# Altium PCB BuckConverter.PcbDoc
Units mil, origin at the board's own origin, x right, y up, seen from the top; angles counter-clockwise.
Board outline 3937.01 x 3149.61 mil, 2 copper layers (Top Layer, Bottom Layer); 153 components, 71 nets, 409 pads, 250 vias.
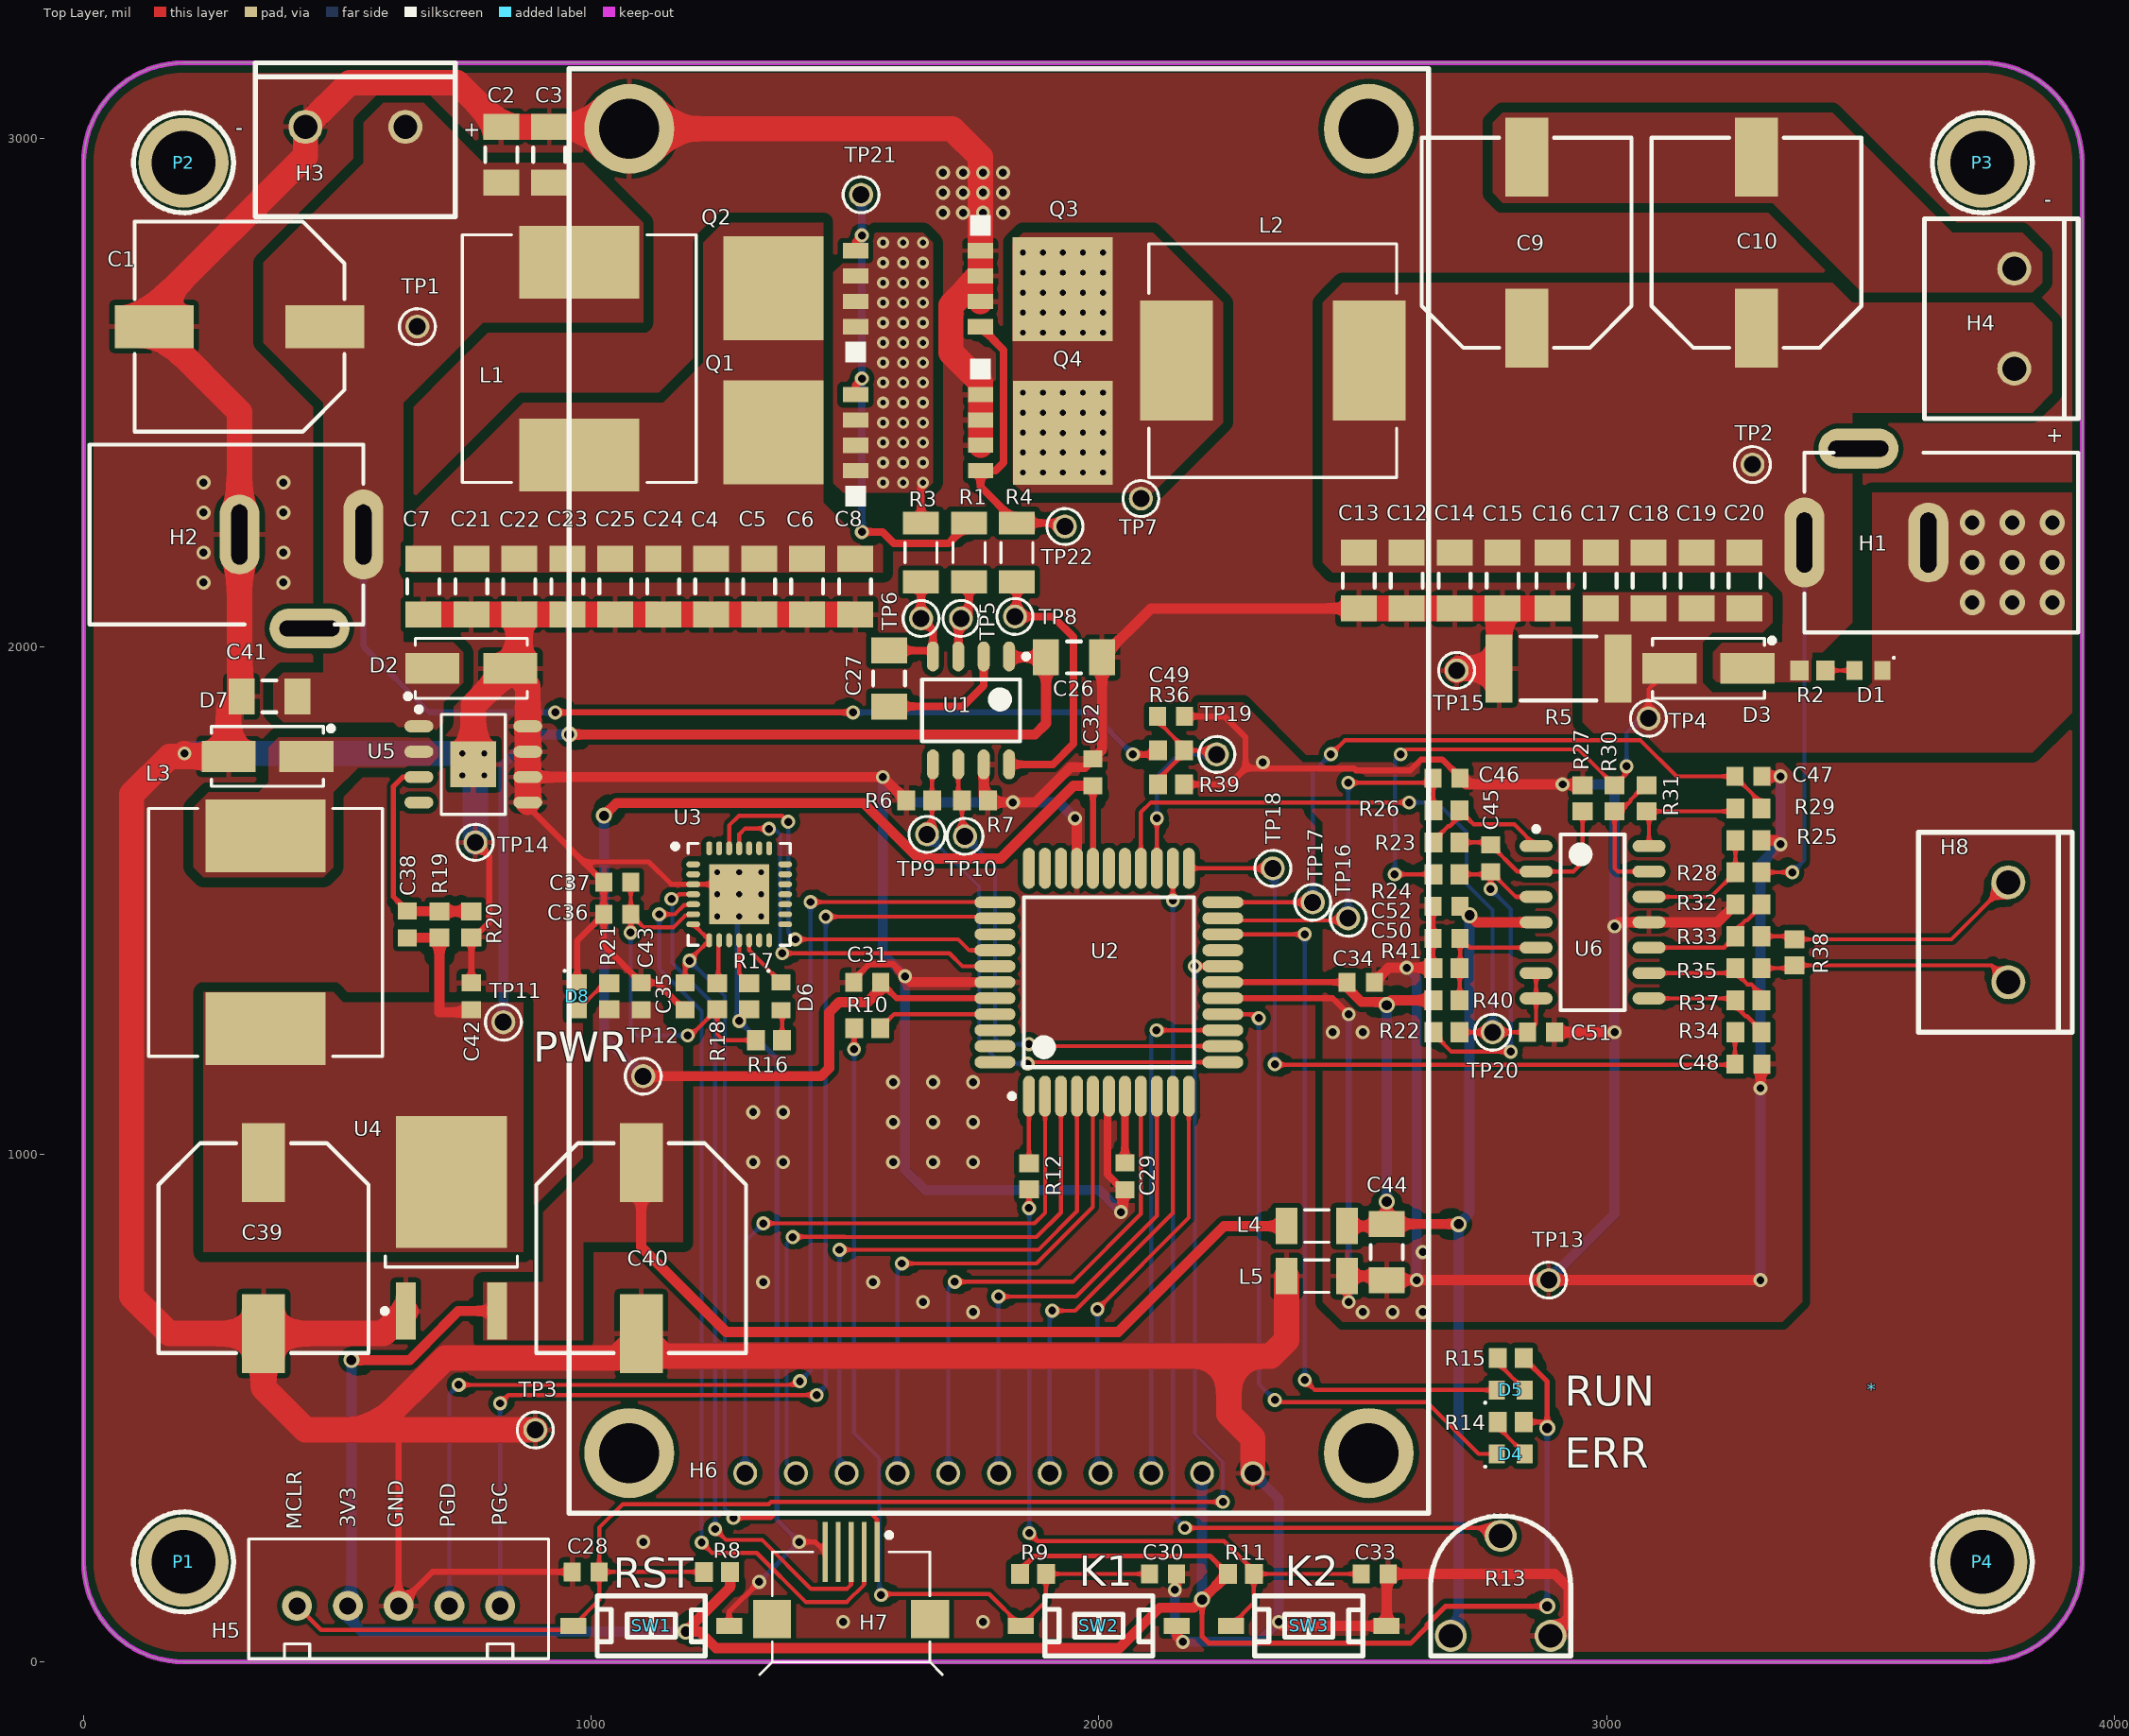
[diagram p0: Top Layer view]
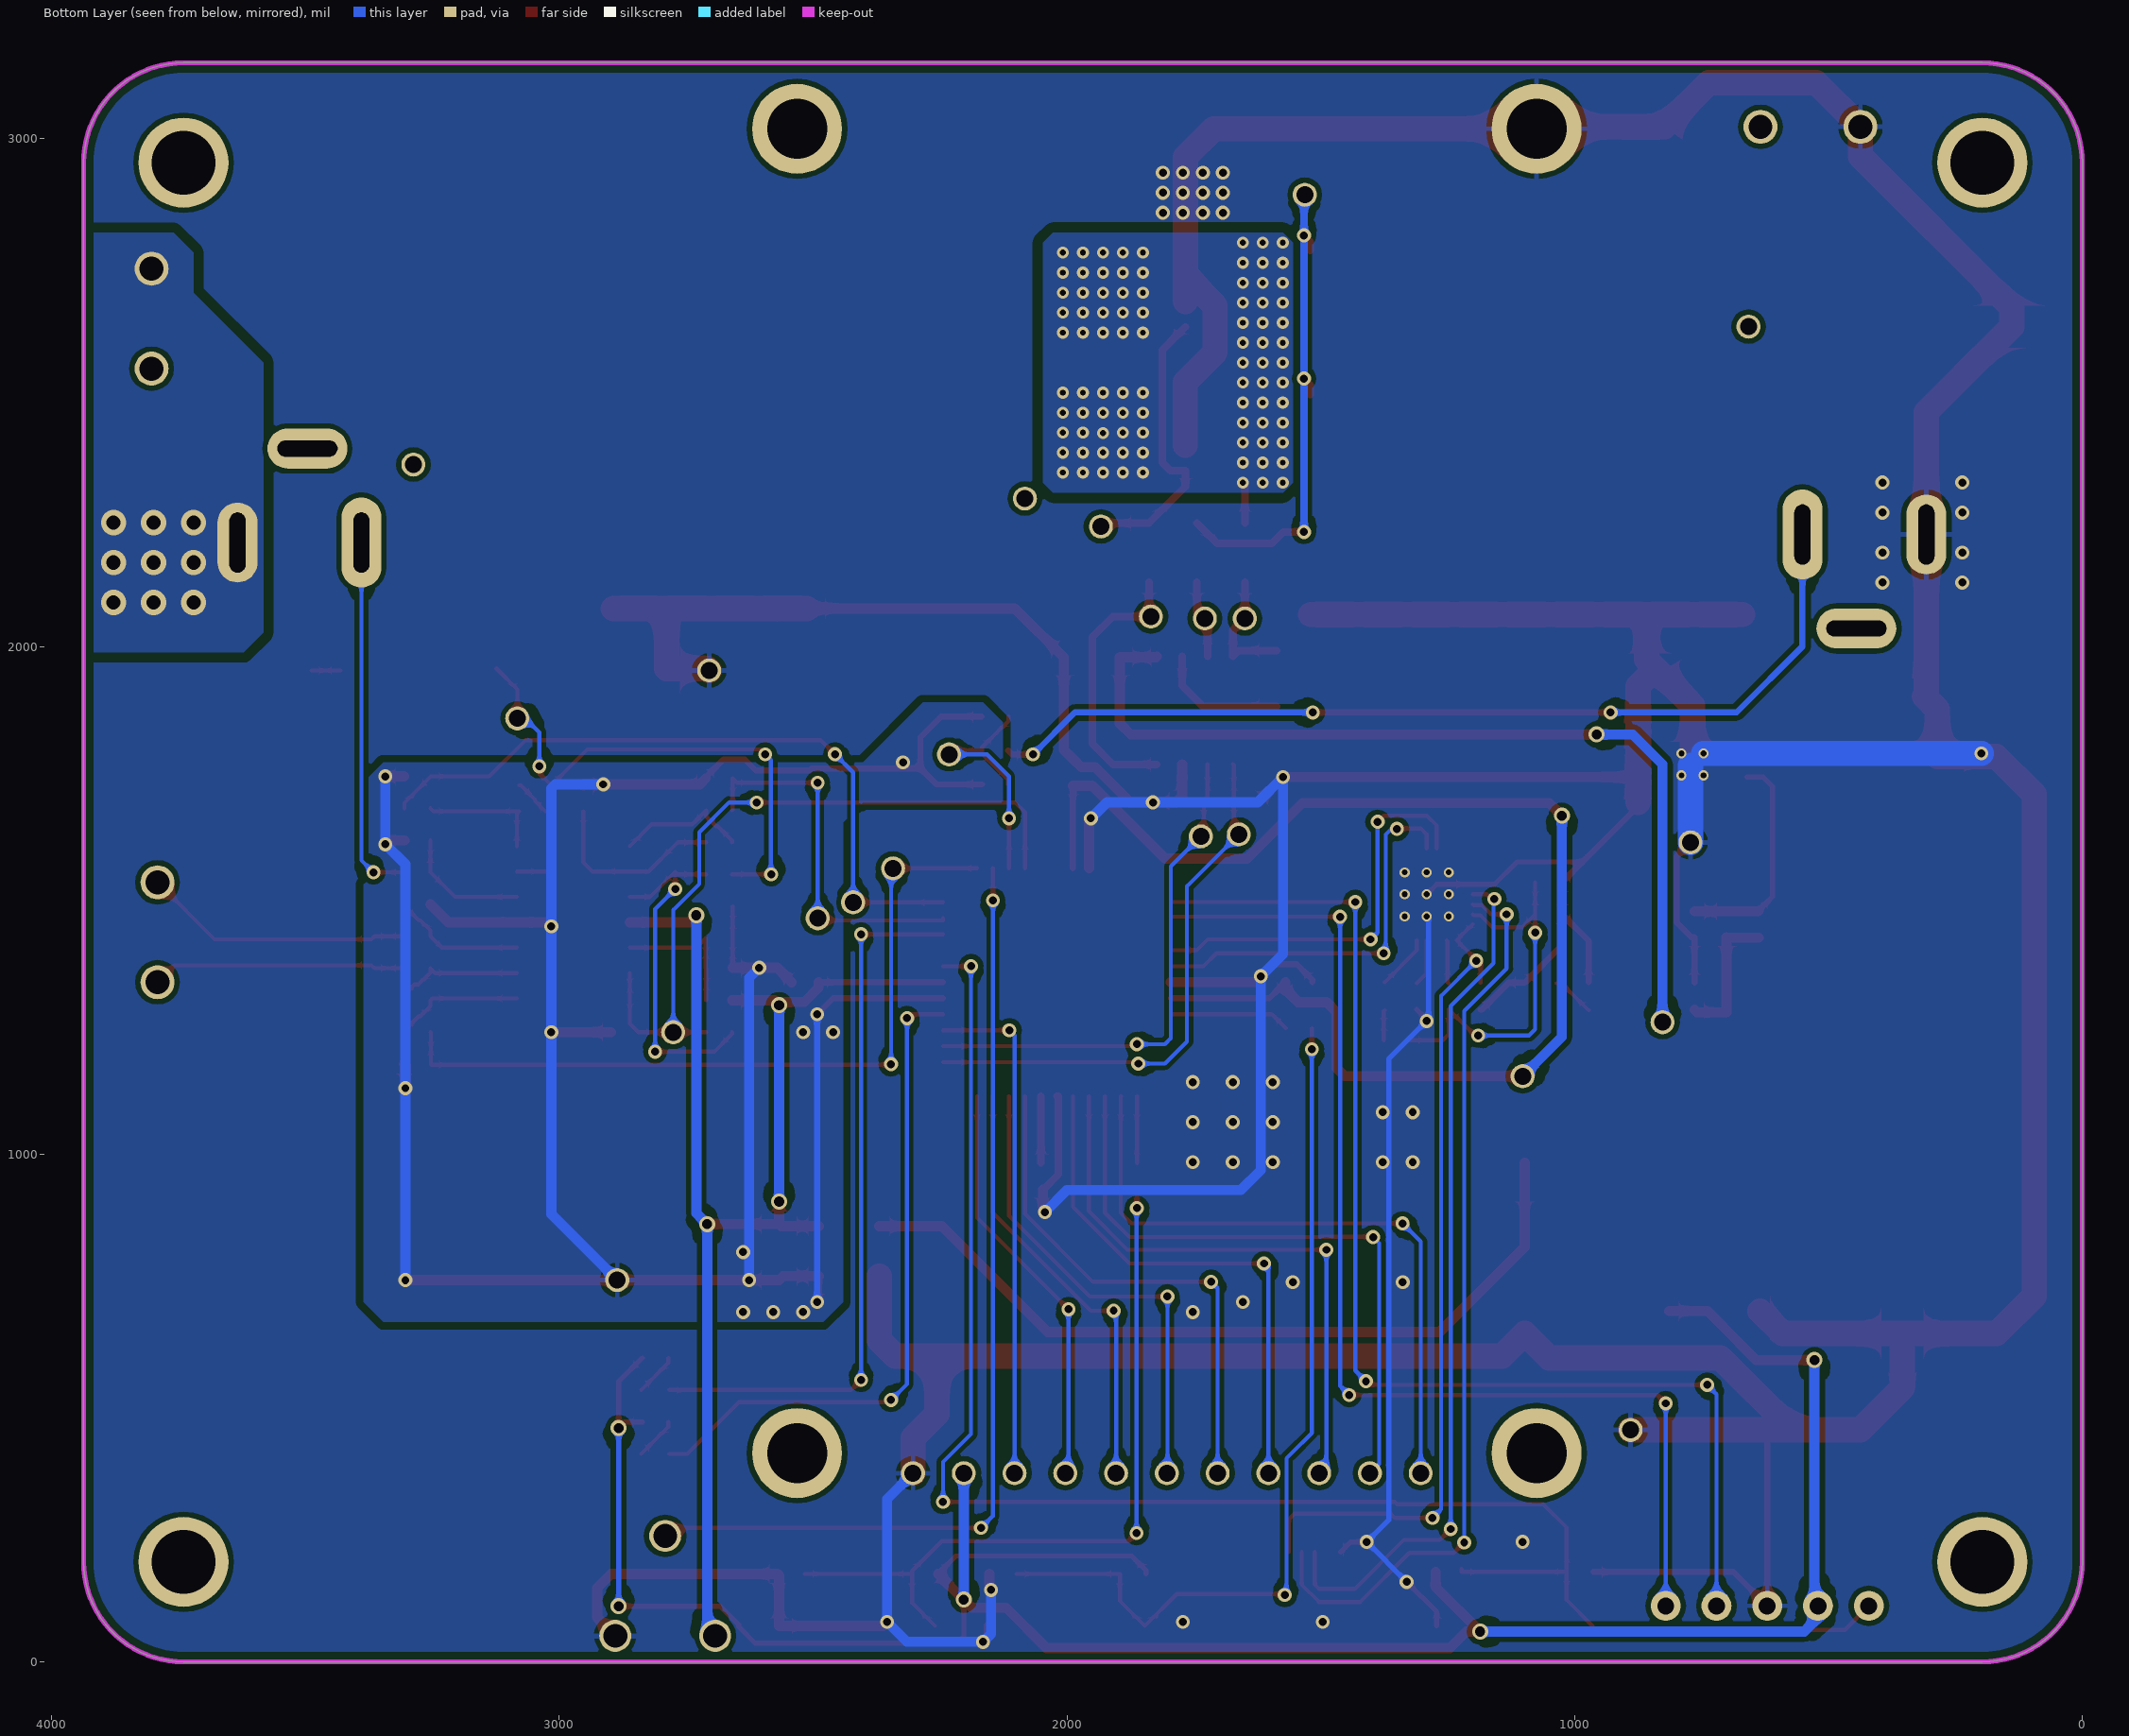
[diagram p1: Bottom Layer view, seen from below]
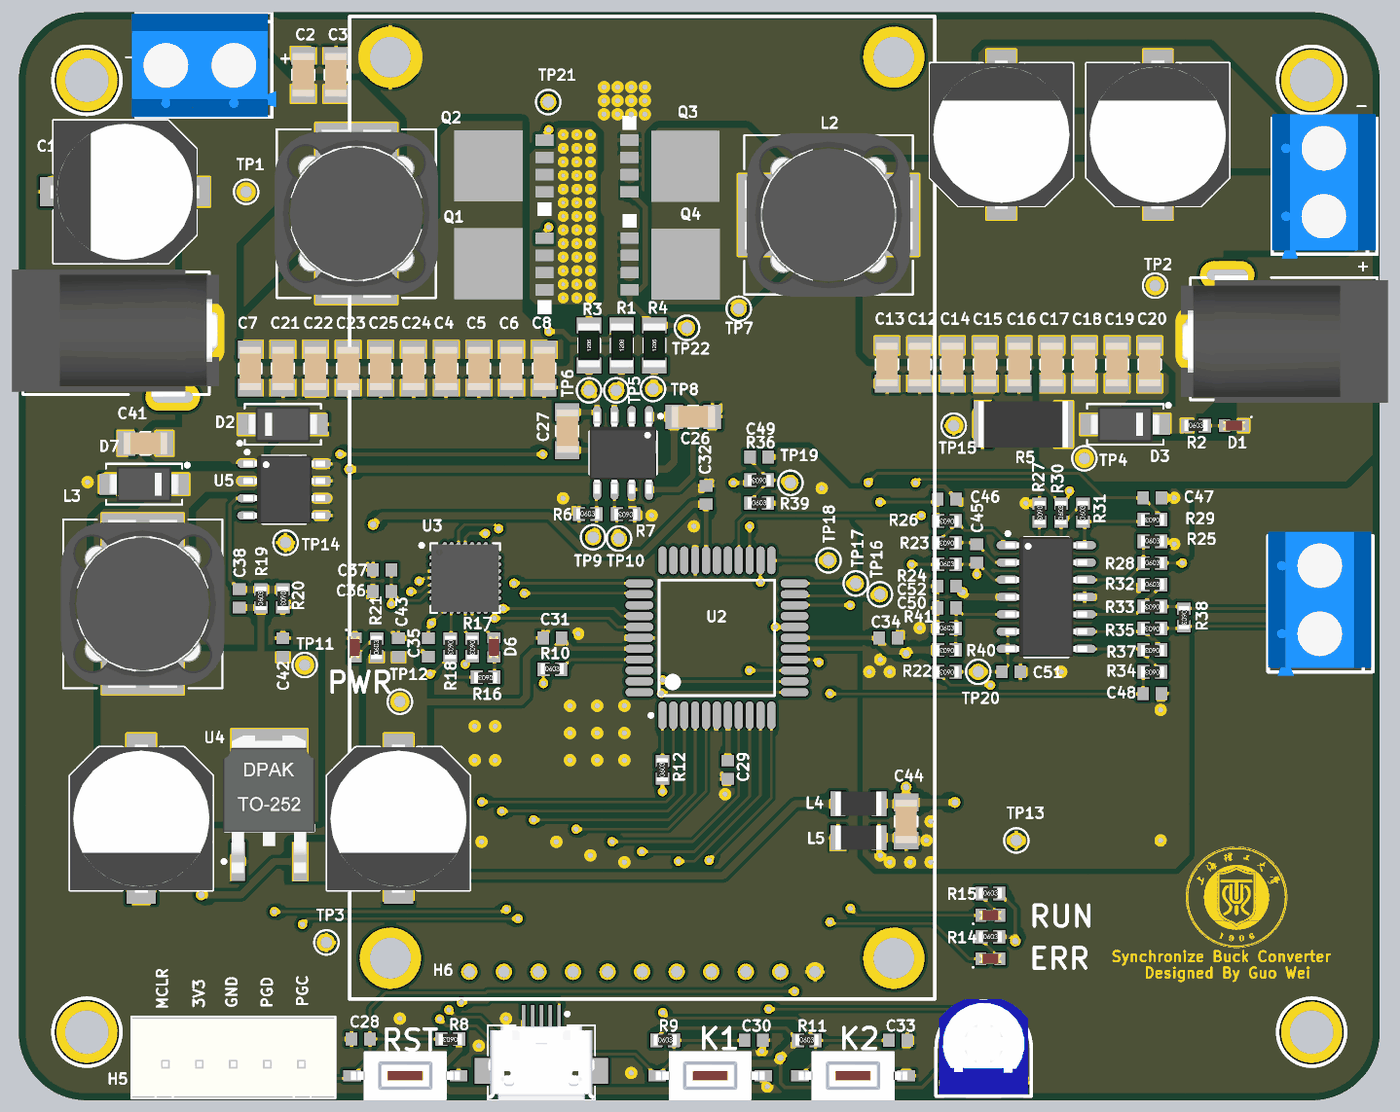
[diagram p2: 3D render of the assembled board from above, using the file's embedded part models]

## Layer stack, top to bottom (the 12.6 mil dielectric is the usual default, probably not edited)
Top Solder: solder mask 0.4, Solder Resist, Dk 3.5
Top Layer: signal copper 1.4
Dielectric 1: dielectric 12.6, FR-4, Dk 4.8
Bottom Layer: signal copper 1.4
Bottom Solder: solder mask 0.4, Solder Resist, Dk 3.5

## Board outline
0,196.85 0,2952.76 cw(c196.85,2952.76) 196.85,3149.61 3740.16,3149.61 cw(c3740.16,2952.76) 3937.01,2952.76 3937.01,196.85 cw(c3740.16,196.85) 3740.16,0 196.85,0 cw(c196.85,196.85)

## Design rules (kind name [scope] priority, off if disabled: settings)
BoardOutlineClearance [All] p1: gap=10 ignorepadtopadclearanceinfootprint=FALSE except(0: Arc-SplitContinuation Track-SplitContinuation SMDPad-SplitContinuation THPad-SplitContinuation Via-SplitContinuation Fill-SplitContinuation Poly-SplitContinuation Region-SplitContinuation Text-SplitContinuation; 19.68: Poly-OutlineEdge Poly-CavityEdge Poly-CutoutEdge Poly-SplitBarrior)
Clearance Power_Clearance [InNetClass('POWER')] p1: gap=10 ignorepadtopadclearanceinfootprint=FALSE except(0: Arc-Hole Track-Hole SMDPad-Hole THPad-Hole Via-Hole Fill-Hole Poly-Hole Region-Hole Text-Hole; 6: SMDPad-SMDPad; 20: Fill-Fill Fill-Poly Fill-Region Poly-Poly Poly-Region Region-Region)
Clearance [All] p2: gap=10 ignorepadtopadclearanceinfootprint=FALSE except(6: SMDPad-SMDPad; 8: Arc-Arc Arc-Track Arc-SMDPad Arc-THPad Arc-Via Arc-Fill Arc-Poly Arc-Region Arc-Text Arc-Hole Track-Track Track-SMDPad Track-THPad Track-Via Track-Fill Track-Poly Track-Region Track-Text Track-Hole SMDPad-THPad THPad-THPad; 15: Fill-Fill Fill-Poly Fill-Region Poly-Poly Poly-Region Region-Region)
ComponentClearance [All] p1 off: gap=10 collisioncheckmode=3 verticalgap=10 showdistances=FALSE
Height [All] p1 off: minheight=0 maxheight=1000 prefheight=500
HoleSize [All] p1: absolutevalues=TRUE maxlimit=1100 minlimit=0.98 maxpercent=80.000 minpercent=20.000
MinimumSolderMaskSliver [InComponent('*')] p1: minsoldermaskwidth=0
PlaneConnect Power [InNetClass('POWER')] p1: planeconnectstyle=Direct reliefexpansion=20 reliefentries=4 reliefconductorwidth=10 reliefairgap=10
PlaneConnect [All] p2: planeconnectstyle=Relief reliefexpansion=20 reliefentries=4 reliefconductorwidth=10 reliefairgap=10
PolygonConnect PolygonConnect_1 [IsVia] p1: connectstyle=Direct reliefconductorwidth=10 reliefentries=4 polygonreliefangle="90 Angle" airgapwidth=10
PolygonConnect Power_Con [InNetClass('POWER')] p2: connectstyle=Direct reliefconductorwidth=10 reliefentries=4 polygonreliefangle="90 Angle" airgapwidth=10
PolygonConnect [All] p3: connectstyle=Relief reliefconductorwidth=10 reliefentries=4 polygonreliefangle="90 Angle" airgapwidth=10
RoutingVias [All] p1: holewidth=28 width=50 viastyle="Through Hole" minholewidth=11.81 minwidth=23.62 maxholewidth=28 maxwidth=50
SolderMaskExpansion [All] p1: expansion=4
Width [All] p1: maxlimit=100 minlimit=6 preferedwidth=8
25 further rules are at their usual default settings.

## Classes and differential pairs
component class Designator: C45 C46 C47 C48 C49 C50 C51 C52 H8 R22 R23 R24 R25 R26 R27 R28 R29 R30 R31 R32 R33 R34 R35 R36 R37 R38 R39 R40 R41 TP16 TP17 TP18 TP19 TP20 U6
net class POWER: 3V3 9V5 A3V3 NetC1_2 NetC9_1 NetC9_2 NetD7_2 NetL2_1 PV

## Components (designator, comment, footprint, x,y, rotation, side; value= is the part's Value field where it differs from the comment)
* "Logo" USST 3523.62,535.43 r0 top
C1 "100uF" CAPAE109103X105N 307.09,2629.92 r0 top
C2 "22uF" CAP1206 822.83,2968.5 r270 top
C3 "22uF" CAP1206 917.32,2968.5 r270 top
C4 "10uF" CAP1206 1236.22,2118.11 r90 top
C5 "10uF" CAP1206 1330.71,2118.11 r90 top
C6 "10uF" CAP1206 1425.2,2118.11 r90 top
C7 "10uF" CAP1206 669.29,2118.11 r90 top
C8 "10uF" CAP1206 1519.68,2118.11 r90 top
C9 "100uF" CAPAE109103X105N 2842.52,2795.28 r270 top
C10 "100uF" CAPAE109103X105N 3295.28,2795.28 r270 top
C12 "10uF" CAP1206 2606.3,2129.92 r90 top
C13 "10uF" CAP1206 2511.81,2129.92 r90 top
C14 "10uF" CAP1206 2700.79,2129.92 r90 top
C15 "10uF" CAP1206 2795.28,2129.92 r90 top
C16 "10uF" CAP1206 2893.7,2129.92 r90 top
C17 "22uF" CAP1206 2988.19,2129.92 r90 top
C18 "22uF" CAP1206 3082.68,2129.92 r90 top
C19 "10uF" CAP1206 3177.17,2129.92 r90 top
C20 "10uF" CAP1206 3271.65,2129.92 r90 top
C21 "10uF" CAP1206 763.78,2118.11 r90 top
C22 "10uF" CAP1206 858.27,2118.11 r90 top
C23 "10uF" CAP1206 952.76,2118.11 r90 top
C24 "10uF" CAP1206 1141.73,2118.11 r90 top
C25 "10uF" CAP1206 1047.24,2118.11 r90 top
C26 "4.7uF" CAP1206 1951,1978.6 r180 top
C27 "4.7uF" CAP1206 1586.61,1937.01 r270 top
C28 "DNP" CAP0603 989.17,177.17 r0 top
C29 "10uF" CAP0603 2051.18,956.69 r270 top
C30 "0.1uF" CAP0603 2125.98,173.23 r0 top
C31 "0.1uF" CAP0603 1543.31,1338.58 r180 top
C32 "0.1uF" CAP0603 1988.19,1751.97 r90 top
C33 "0.1uF" CAP0603 2543.31,173.23 r0 top
C34 "0.1uF" CAP0603 2515.75,1338.58 r0 top
C35 "1uF" CAP0603 1185.04,1311.02 r90 top
C36 "4.7uF" CAP0603 1051.18,1472.44 r0 top
C37 "0.1uF" CAP0603 1051.18,1535.43 r0 top
C38 "33nF" CAP0603 637.8,1452.76 r90 top
C39 "100uF" CAPAE109103X105N 354.33,814.96 r90 top
C40 "100uF" CAPAE109103X105N 1098.43,814.96 r90 top
C41 "10uF" CAP1206 366.14,1901.57 r0 top
C42 "0.1uF" CAP0603 763.78,1311.02 r90 top
C43 "0.1uF" CAP0603 1098.43,1311.02 r90 top
C44 "22uF" CAP1206 2566.93,807.09 r270 top
C45 "DNP" CAP0603 2771.65,1582.68 r90 top
C46 "10nF" CAP0603 2685.04,1740.16 r0 top
C47 "10nF" CAP0603 3279.53,1744.09 r0 top
C48 "10nF" CAP0603 3279.53,1177.17 r0 top
C49 "10nF" CAP0603 2141.73,1862.2 r0 top
C50 "0.1uF" CAP0603 2685.04,1425.2 r180 top
C51 "0.1uF" CAP0603 2871.06,1240.16 r0 top
C52 "0.1uF" CAP0603 2685.04,1488.19 r180 top
D1 "PWR" LED0603 3515.75,1952.76 r0 top
D2 "SMAJ90A" SMA 763.78,1956.69 r180 top
D3 "SMAJ90A" SMA 3200.79,1956.69 r0 top
D4 "ERR" LED0603 2811.02,409.45 r180 top
D5 "RUN" LED0603 2811.02,535.43 r180 top
D6 "LED" LED0603 1374.02,1311.02 r90 top
D7 "SS310" SMA 362.2,1783.46 r0 top
D8 "PWR" LED0603 972.44,1311.02 r90 top
H1 "PWR-2.5" PWR-2.5 3633.86,2204.72 r180 top
H2 "PWR-2.5" PWR-2.5 307.09,2220.47 r0 top
H3 "" KF301 535.43,3023.62 r180 top
H4 "" KF301 3803.15,2645.67 r90 top
H5 "xh2.54" XH2.54_5A 620.47,110.24 r0 top
H6 "LCD" LCD-2.4' 2303.15,371.65 r90 top
H7 "USB-5p" USB_Micro 1511.81,-0.31 r270 top
H8 "" KF301 3791.34,1437.01 r90 top
L1 "10uH" CDRH125 976.38,2566.93 r270 top
L2 "15uH" CDRH125 2342.52,2562.99 r0 top
L3 "100uH" CDRH125 358.27,1437.01 r270 top
L4 "Inductor" IND1206 2429.13,858.27 r0 top
L5 "Inductor" IND1206 2429.13,759.84 r0 top
P1 "Pad" PAD320R450 196.85,196.85 r0 top
P2 "Pad" PAD320R450 196.85,2952.76 r0 top
P3 "Pad" PAD320R450 3740.16,2952.76 r0 top
P4 "Pad" PAD320R450 3740.16,196.85 r0 top
Q1 "BSC123N08NS3G" QFN5x6 1405.52,2421.06 r90 top
Q2 "BSC123N08NS3G" QFN5x6 1405.52,2704.69 r90 top
Q3 "BSC123N08NS3G" QFN5x6 1881.5,2704.69 r270 top
Q4 "BSC123N08NS3G" QFN5x6 1881.89,2421.26 r270 top
R1 "2R" RES1206 1744.09,2185.04 r90 top
R2 "2k" RES0603 3405.51,1952.76 r0 top
R3 "2R" RES1206 1649.61,2185.04 r90 top
R4 "2R" RES1206 1838.58,2185.04 r90 top
R5 "R050" RESC6432X07N 2905.51,1956.69 r0 top
R6 "10k" RES0603 1645.67,1696.85 r0 top
R7 "10k" RES0603 1755.91,1696.85 r180 top
R8 "10k" RES0603 1248.03,177.17 r180 top
R9 "10k" RES0603 1870.08,173.23 r0 top
R10 "0R" RES0603 1543.31,1248.03 r0 top
R11 "10k" RES0603 2279.53,173.23 r0 top
R12 "0R" RES0603 1862.2,956.69 r90 top
R13 "RPot" RM065 2791.34,287.4 r0 top
R14 "470R" RES0603 2811.02,472.44 r0 top
R15 "470R" RES0603 2811.02,598.43 r0 top
R16 "1k" RES0603 1350.39,1224.41 r180 top
R17 "10k" RES0603 1311.02,1311.02 r270 top
R18 "4.7k" RES0603 1248.03,1311.02 r270 top
R19 "30k" RES0603 700.79,1452.76 r90 top
R20 "4.7k" RES0603 763.78,1452.76 r270 top
R21 "1k" RES0603 1035.43,1311.02 r90 top
R22 "12k" RES0603 2685.04,1240.16 r180 top
R23 "12k" RES0603 2685.04,1614.17 r180 top
R24 "1k" RES0603 2685.04,1551.18 r0 top
R25 "1k" RES0603 3279.53,1618.11 r0 top
R26 "10k" RES0603 2685.04,1677.17 r180 top
R27 "1k" RES0603 2952.76,1700.79 r270 top
R28 "10k" RES0603 3279.53,1555.12 r0 top
R29 "10k" RES0603 3279.53,1681.1 r180 top
R30 "10k" RES0603 3015.75,1700.79 r90 top
R31 "1k" RES0603 3078.74,1700.79 r90 top
R32 "1k" RES0603 3279.53,1492.13 r0 top
R33 "10k" RES0603 3279.53,1429.13 r180 top
R34 "10k" RES0603 3279.53,1240.16 r180 top
R35 "10k" RES0603 3279.53,1366.14 r180 top
R36 "12k" RES0603 2141.73,1795.28 r180 top
R37 "1k" RES0603 3279.53,1303.15 r180 top
R38 "5k" RES0603 3370.08,1397.64 r270 top
R39 "1k" RES0603 2141.73,1728.35 r0 top
R40 "10k" RES0603 2685.04,1303.15 r180 top
R41 "10k" RES0603 2685.04,1366.14 r0 top
SW1 "RST" "SW-PB SMD" 1118.11,70.87 r270 top
SW2 "K1" "SW-PB SMD" 2000,70.87 r270 top
SW3 "K2" "SW-PB SMD" 2413.39,70.87 r270 top
TP1 "TP" PAD85R 657.48,2629.92 r0 top
TP2 "TP" PAD85R 3287.4,2358.27 r90 top
TP3 "TP" PAD85R 889.76,456.69 r90 top
TP4 "TP" PAD85R 3082.68,1858.27 r90 top
TP5 "TP" PAD85R 1728.35,2055.12 r90 top
TP6 "TP" PAD85R 1649.61,2055.12 r90 top
TP7 "TP" PAD85R 2082.68,2291.34 r90 top
TP8 "TP" PAD85R 1834.65,2059.06 r90 top
TP9 "TP" PAD85R 1661.42,1629.92 r0 top
TP10 "TP" PAD85R 1736.22,1625.98 r0 top
TP11 "TP" PAD85R 826.77,1259.84 r90 top
TP12 "TP" PAD85R 1102.36,1153.54 r90 top
TP13 "TP" PAD85R 2885.83,751.97 r90 top
TP14 "TP" PAD85R 771.65,1614.17 r90 top
TP15 "TP" PAD85R 2704.72,1952.76 r90 top
TP16 "TP" PAD85R 2491,1464.6 r90 top
TP17 "TP" PAD85R 2421.26,1496.06 r90 top
TP18 "TP" PAD85R 2342.52,1562.99 r90 top
TP19 "TP" PAD85R 2232.28,1787.4 r90 top
TP20 "TP" PAD85R 2775.59,1240.16 r90 top
TP21 "TP" PAD85R 1531.5,2889.76 r90 top
TP22 "TP" PAD85R 1933.07,2236.22 r90 top
U1 "UCC27212" SOP127P600X175-8N 1748.03,1874.02 r270 top
U2 "dsPIC33EP64GS504" TQFP-PT44_M 2019.68,1338.58 r90 top
U3 "CP2102" QFN28 1291.34,1511.81 r0 top
U4 "AMS1086CD" DPAK228P1003X238-3N 724.41,854.33 r90 top
U5 "XL7005A" SOIC127P600X175_HS-9N 767.72,1767.72 r0 top
U6 "TLV2374" SOIC127P600X175-14N 2972.44,1456.69 r0 top

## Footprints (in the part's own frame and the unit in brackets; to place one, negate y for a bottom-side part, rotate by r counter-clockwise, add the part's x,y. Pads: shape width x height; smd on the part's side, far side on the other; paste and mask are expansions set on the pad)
CAP0603 [mm] "Chip Capacitor, 2-Leads, Body 1.60x0.80mm, IPC Medium Density"
  rect 0.85x0.95 smd: 1(-0.675,0) 2(0.675,0)
  body extent -0.85,-0.45 0.85,0.45, height 0.55
CAP1206 [mm] "Chip Capacitor, 2-Leads, Body 3.20x1.60mm, IPC Medium Density"
  rect 1.3x1.8 smd: 1(-1.4,0) 2(1.4,0)
  silkscreen extent -0.35,-0.8 0.35,0.8, body extent -1.6,-0.8 1.6,0.8, height 0.74
CAPAE109103X105N [mm] "Aluminum Electrolytic Capacitor, Body 10.30x10.30x10.50mm, IPC Medium Density"
  rect 3.95x2.15 smd: 1(-4.275,0) 2(4.275,0)
  silkscreen extent -5.25,-5.25 5.25,5.25, body extent -5.45,-5.25 5.45,5.25, height 10.5
CDRH125 [mm] "Molded Inductor, 2-Leads, Body 12.00x11.70mm, IPC Medium Density"
  rect 3.65x6 smd: 1(-4.825,0) 2(4.825,0)
  silkscreen extent -6.2,-5.85 6.2,5.85, body extent -6.17,-6 6.17,6, height 6.3
DPAK228P1003X238-3N [mm] "D-PAK, 3-Pads, Body 6.15x6.66mm (max), IPC Medium Density"
  rect 2.85x1 smd: 1(-4.15,2.28) 3(-4.15,-2.28)
  rect 6.6x5.55 smd: 2(2.3,0)
  silkscreen extent -4.27,-3.3 -1.4,3.45, body extent -5,-3.34 5.1,3.39, height 2.37
IND1206 [mm] "Chip Inductor, 2-Leads, Body 3.20x1.60mm, IPC Medium Density"
  rect 1.09x1.82 smd: 1(-1.51,0) 2(1.51,0)
  silkscreen extent -0.6,-0.81 0.6,0.81, body extent -1.7,-0.9 1.7,0.9, height 0.6
KF301 [mm]
  round 1.7 hole 1.2: 1(-2.5,0) 2(2.5,0)
  silkscreen extent -5,-3.2 5,4.5, body extent -5.3,-3.1 5.3,4.5, height 10
LCD-2.4' [mm]
  round 4.5 hole 3: 0(1,31.2) 0(1,-5.8) 0(67.26,-5.8) 0(67.26,31.2)
  round 1.2 hole 0.85: 1(0,0) 2(0,2.54) 3(0,5.08) 4(0,7.62) 5(0,10.16) 6(0,12.7) 7(0,15.24) 8(0,17.78) 9(0,20.32) 10(0,22.86) 11(0,25.4)
  silkscreen extent -2,-8.8 70.26,34.2
LED0603 [mm] "Chip Diode, 2-Leads, Body 1.60x0.80mm, IPC Medium Density"
  rect 0.8x0.95 smd: 1(-0.7,0) 2(0.7,0)
  silkscreen extent 1.22,0.59 1.32,0.68, body extent -0.81,-0.4 0.81,0.4, height 0.6
PAD85R [mm]
  round 1.2 hole 0.85: 1(0,0)
  silkscreen extent -0.9,-0.9 0.9,0.9
PAD320R450 [mm]
  round 4.5 hole 3.2: 1(0,0)
  silkscreen extent -2.5,-2.5 2.5,2.5
PWR-2.5 [mm]
  oval 2x4.5 hole 0.8 slot 3 at 90 deg: 1(6.2,0)
  oval 2x4 hole 0.8 slot 3 at 90 deg: 2(0,0)
  oval 4x2 hole 0.8 slot 3 at 0 deg: 3(3.5,-4.7)
  silkscreen extent -7.5,-4.5 6.2,4.5, body extent -8.3,-4.7 6.9,4.7, height 11
QFN5x6 [mil]
  rect 30x50 smd paste+1.5 mask+1.5: 1(-75,-115) 2(-25,-115) 3(25,-115) 4(75,-115)
  rect 204.72x196.85 smd paste+0.64 mask+0.64: 5(0.79,46.85)
  silkscreen extent -145,-135 -105,-95
QFN28 [mm] "PQFN, 28-Leads, Body 5.00x5.00mm, Pitch 0.50mm, Thermal Pad 3.10x3.10mm, IPC Medium Density"
  oval 0.7x0.3 smd: 1(-2.3,1.5) 2(-2.3,1) 3(-2.3,0.5) 4(-2.3,0) 5(-2.3,-0.5) 6(-2.3,-1) 7(-2.3,-1.5) 15(2.3,-1.5) 16(2.3,-1) 17(2.3,-0.5) 18(2.3,0) 19(2.3,0.5) 20(2.3,1) 21(2.3,1.5)
  oval 0.3x0.7 smd: 8(-1.5,-2.3) 9(-1,-2.3) 10(-0.5,-2.3) 11(0,-2.3) 12(0.5,-2.3) 13(1,-2.3) 14(1.5,-2.3) 22(1.5,2.3) 23(1,2.3) 24(0.5,2.3) 25(0,2.3) 26(-0.5,2.3) 27(-1,2.3) 28(-1.5,2.3)
  rect 3x3 smd: 29(0,0)
  silkscreen extent -3.32,-2.55 2.55,2.55, body extent -2.5,-2.5 2.5,2.5, height 1
RES0603 [mm] "Chip Resistor, 2-Leads, Body 1.60x0.80mm, IPC Medium Density"
  rect 0.9x1 smd: 1(-0.65,0) 2(0.65,0)
  body extent -0.85,-0.38 0.85,0.42, height 0.56
RES1206 [mm] "Chip Resistor, 2-Leads, Body 3.20x1.60mm, IPC Medium Density"
  rect 1.15x1.8 smd: 1(-1.475,0) 2(1.475,0)
  silkscreen extent -0.5,-0.8 0.5,0.8, body extent -1.6,-0.8 1.6,0.8, height 0.6
RESC6432X07N [mm] "Chip Resistor, 2-Leads, Body 6.40x3.20mm, IPC Medium Density"
  rect 1.35x3.4 smd: 1(-2.975,0) 2(2.975,0)
  silkscreen extent -1.9,-1.6 1.9,1.6, body extent -3.3,-1.7 3.3,1.7, height 0.7
RM065 [mm]
  round 1.6 hole 1.2: 1(-2.5,-6) 2(0,-1) 3(2.5,-6)
  silkscreen extent -3.5,-7 3.5,0, body extent -3.25,-7.14 3.25,0.1, height 7.7
SMA [mm] "Molded Diode, 2-Leads, Body 5.20x2.60mm, IPC Medium Density"
  rect 2.7x1.55 smd: 1(-1.95,0) 2(1.95,0)
  silkscreen extent -2.8,-1.5 3.3,1.52, body extent -2.6,-1.3 2.6,1.3, height 2
SOIC127P600X175-14N [mm] "SOIC, 14-Leads, Body 8.65x3.90mm, Pitch 1.27mm, IPC Medium Density"
  oval 1.65x0.6 smd: 1(-2.825,3.81) 2(-2.825,2.54) 3(-2.825,1.27) 4(-2.825,0) 5(-2.825,-1.27) 6(-2.825,-2.54) 7(-2.825,-3.81) 8(2.825,-3.81) 9(2.825,-2.54) 10(2.825,-1.27) 11(2.825,0) 12(2.825,1.27) 13(2.825,2.54) 14(2.825,3.81)
  silkscreen extent -2.95,-4.4 1.6,4.78, body extent -3,-4.4 3,4.4, height 1.75
SOIC127P600X175_HS-9N [mm] "SOIC, 8-Leads, Body 4.90x3.91mm, Pitch 1.27mm, Thermal Pad 2.30x2.30mm, IPC Medium Density"
  oval 1.45x0.6 smd: 1(-2.725,1.905) 2(-2.725,0.635) 3(-2.725,-0.635) 4(-2.725,-1.905) 5(2.725,-1.905) 6(2.725,-0.635) 7(2.725,0.635) 8(2.725,1.905)
  rect 2.3x2.3 smd: 9(0,0)
  silkscreen extent -2.85,-2.5 1.6,2.88, body extent -3,-2.5 3,2.5, height 1.75
SOP127P600X175-8N [mm] "SOP, 8-Leads, Body 4.90x3.90mm, Pitch 1.27mm, IPC Medium Density"
  oval 1.5x0.6 smd: 1(-2.7,1.905) 2(-2.7,0.635) 3(-2.7,-0.635) 4(-2.7,-1.905) 5(2.7,-1.905) 6(2.7,-0.635) 7(2.7,0.635) 8(2.7,1.905)
  silkscreen extent -2.82,-2.45 1.55,2.88, body extent -3,-2.45 3,2.45, height 1.75
"SW-PB SMD" [mm]
  rect 0.8x1.3 smd: 1(0,3.9) 2(0,-3.9)
  silkscreen extent -1.5,-2.7 1.5,2.7, body extent -1.8,-4 1.8,4, height 2.5
TQFP-PT44_M [mm] "Thin QFP, 44-Leads, Body 10x10mm, Pitch 0.8mm, IPC Low Density"
  oval 2.05x0.6 smd: 1(-5.7,4) 2(-5.7,3.2) 3(-5.7,2.4) 4(-5.7,1.6) 5(-5.7,0.8) 6(-5.7,0) 7(-5.7,-0.8) 8(-5.7,-1.6) 9(-5.7,-2.4) 10(-5.7,-3.2) 11(-5.7,-4) 23(5.7,-4) 24(5.7,-3.2) 25(5.7,-2.4) 26(5.7,-1.6) 27(5.7,-0.8) 28(5.7,0) 29(5.7,0.8) 30(5.7,1.6) 31(5.7,2.4) 32(5.7,3.2) 33(5.7,4)
  oval 0.6x2.05 smd: 12(-4,-5.7) 13(-3.2,-5.7) 14(-2.4,-5.7) 15(-1.6,-5.7) 16(-0.8,-5.7) 17(0,-5.7) 18(0.8,-5.7) 19(1.6,-5.7) 20(2.4,-5.7) 21(3.2,-5.7) 22(4,-5.7) 34(4,5.7) 35(3.2,5.7) 36(2.4,5.7) 37(1.6,5.7) 38(0.8,5.7) 39(0,5.7) 40(-0.8,5.7) 41(-1.6,5.7) 42(-2.4,5.7) 43(-3.2,5.7) 44(-4,5.7)
  silkscreen extent -5.82,-4.25 4.25,4.97, body extent -5,-5 5,5, height 1.2
USB_Micro [mm]
  rect 3x0.25 smd: 1(-5.508,1.3) 2(-5.508,0.65) 3(-5.508,0) 4(-5.508,-0.65) 5(-5.508,-1.3)
  rect 1.9x1.9 smd: ""(-2.15,3.95) ""(-2.15,-3.95)
  silkscreen extent -6.47,-4.57 0.63,4.57, body extent -5.44,-3.99 -0.01,3.99, height 2.77
USST [mil]
XH2.54_5A [mm]
  round 1.5 hole 0.85: 1(-5.08,0) 2(-2.54,0) 3(0,0) 4(2.54,0) 5(5.08,0)
  silkscreen extent -7.5,-2.65 7.5,3.35, body extent -7.45,-2.52 7.45,3.23, height 7

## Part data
C1 C9 C10 C39 C40: library part CAP_Pol, "cap pol", Capacitance Value=47uF, Rated Voltage=50V, Tolerance="+\- 10%"
C2 C3 C4 C5 C6 C7 C8 C12 C13 C14 C15 C16 C17 C18 C19 C20 C21 C22 C23 C24 C25 C26 C27 C28 C29 C35 C36 C38 C41 C44 C45 C46 C47 C48 C49: library part CAP, "CAP NON-POL", Capacitance Value=0.1uF, Rated Voltage=50V, Tolerance=+/-10%
C30 C31 C32 C33 C34 C37 C42 C43 C50 C51 C52: library part CAP, "CAP NON-POL", Rated Voltage=50V, Tolerance=+/-10%
D1 D4 D5 D8: library part LED, "led"
D2 D3 D7: library part Diode, "diode"
D6: "led"
H3 H4 H8: library part Connector-2P
H5: library part XH2.54_5P, "pitch2.54"
H6: library part LCD_2.4', "2.4' TFT Module"
H7: library part USB_5P, "USB_5P"
L1 L2 L3: library part Inductor, "Inductor"
P1 P2 P3 P4: "PAD"
Q1 Q2 Q3 Q4: library part MOS-N4, "N Channel MOSFET"
R1 R2 R3 R4 R5 R6 R7 R8 R9 R10 R11 R12 R14 R15 R16 R17 R18 R19 R20 R21 R22 R23 R24 R25 R26 R27 R28 R29 R30 R31 R32 R33 R34 R35 R36 R37 R38 R39 R40 R41: library part RES, "res"
R13: "Potentiometer"
SW1 SW2 SW3: library part SW-PB, "push button"
TP1 TP2 TP3 TP4 TP5 TP6 TP7 TP8 TP9 TP10 TP11 TP12 TP13 TP14 TP15 TP16 TP17 TP18 TP19 TP20 TP21 TP22: library part Test_Point, "test point"
U1: library part UCC27211, "UCC2721x 120-V Boot, 4-A Peak, High-Frequency High-Side and Low-Side Driver"
U4: "LDO"
U5: "0.4A 150KHz 80V Buck DC to DC Converter"
U6: "550uA/Ch 3-MHz RAIL-TO-RAIL INPUT/OUTPUT OPERATIONAL AMPLIFIERS"

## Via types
v1: diameter 27.56, hole 15.75, Top Layer to Bottom Layer, 128 vias
v2: diameter 23.62, hole 11.81, Top Layer to Bottom Layer, 89 vias
v3: diameter 19.68, hole 11.81, Top Layer to Bottom Layer, 13 vias
v4: diameter 31.5, hole 19.68, Top Layer to Bottom Layer, 11 vias
v5: diameter 50, hole 28, Top Layer to Bottom Layer, 9 vias

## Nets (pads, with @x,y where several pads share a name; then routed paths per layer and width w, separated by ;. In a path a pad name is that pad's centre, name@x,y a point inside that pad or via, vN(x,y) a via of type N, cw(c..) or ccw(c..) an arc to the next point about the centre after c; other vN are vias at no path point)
3V3: C31.1 C32.1 C40.2 C43.1 H5.2 H6.2 L4.1 R8.1 R9.1 R11.1 R14.2 R15.2 R21.1 TP12.1 U2.29 U2.40 U4.3 | length 9085.9
  Top Layer w10: R9.1 1844.49,180.66 1872.42,208.6 2218.57,208.6 R11.1 ; v4(2203.15,122.76) 2203.15,50.45 2217,36.6 2614,36.6 2646.42,69.02 2646.42,73.02 2682.99,109.6 v4(2883,109.6) ; R14.2 2871.16,472.44 v4(2883,460.6) 2883,552.04 R15.2
  Top Layer w12: C31.1 1601.38,1307.09 U2.40 ; U2.29 C32.1
  Top Layer w20: v4(527.56,594.49) 642.26,594.49 674.33,626.56 674.33,627.09 738.19,690.94 U4.3 ; v4(1025,1666.6) 1050,1691.6 1536,1691.6 1645.24,1582.36 1806.77,1582.36 1949.8,1725.39 C32.1 ; C40.2 1098.43,817.17 1266,649.6 2037.66,649.6 2246.33,858.27 L4.1 ; TP12.1 1452.76,1153.54 1468.5,1169.29 1468.5,1279.53 1488.19,1299.21 1544.61,1299.21 1569.88,1324.48 C31.1 ; R8.1 1273.62,147.22 v4(1186,59.6) 1213.3,59.6 1245.97,26.93 2039.98,26.93 2119.67,106.61 2187.01,106.61 v4(2203.15,122.76) ; v4@2203.31,122.6 R11.1
  Bottom Layer w10: v4(2883,109.6) v4(2883,460.6)
  Bottom Layer w20: v4(527.56,594.49) 527.56,117.32 H5.2 520.47,87.13 548,59.6 v4(1186,59.6) ; v4(1025,1666.6) 1025,1230.91 TP12.1 ; v4(2203.15,122.76) H6.2
9V5: C26.2 C38.1 C39.2 C42.1 L3.2 R19.1 TP11.1 U1.1 U4.2 | length 2090.1
  Top Layer w20: C38.1 699.8,1426.18 R19.1 700.79,1279.53 758.86,1279.53 C42.1 ; v4(956.69,1826.77) 1874.02,1826.77 1895.88,1848.64 C26.2 1824.75,1978.6 U1.1
  Bottom Layer w20: TP11.1 826.77,1767.72 885.83,1826.77 v4(956.69,1826.77)
A3V3: C34.1 C44.1 C52.1 L4.2 R13.1 R40.2 U2.17 U6.4 | length 2656.5
  Top Layer w12: U2.17 C34.1
  Top Layer w20: L4.2 2562.99,858.27 C44.1 ; C34.1 2489.17,1328.02 2517.31,1299.88 2560.72,1299.88 v4(2567,1293.6) ; v4(2566.93,906.53) C44.1 ; v4@2575.55,1303.15 R40.2 ; v4(2708.61,862.2) C44.1 ; v4(2730,1470.6) 2743.91,1456.69 U6.4
  Bottom Layer w20: v4(2566.93,906.53) 2567,906.6 v4(2567,1293.6) ; R13.1 2708.61,66.87 v4(2708.61,862.2) 2730,883.6 v4(2730,1470.6)
AGND: C34.2 C44.2 C46.2 C47.2 C48.2 C49.2 C50.2 C51.2 C52.2 L5.2 R25.2 R27.1 R32.1 R39.2 R41.1 TP13.1 U2.16 U6.11 | length 6237
  Top Layer w8: R41.1@2658.46,1367.13 C50.2 C52.2
  Top Layer w12: R39.2 2257.09,1728.35 2288.67,1759.93 ; C49.2 2247.39,1862.2 2288.67,1820.93 2288.67,1759.93 ; U2.16 2460.63,1307.09 v1(2492.13,1275.59) ; L5.2 2488.58,712.2 v1(2492.13,708.66) ; C46.2 2711.61,1742.24 2676.67,1777.18 2634.58,1777.18 2613,1755.6 2506.29,1755.6 2501.96,1759.93 2288.67,1759.93
  Top Layer w20: L5.2 2559.06,759.84 C44.2 v1(2625.98,751.97) TP13.1 v1(3303.15,751.97) ; C34.2 2570.87,1367.13 v1(2606.3,1367.13) R41.1@2658.46,1367.13 ; C46.2 2723.43,1728.35 v1(2913.39,1728.35) 2950.79,1728.35 R27.1 ; C51.2 v1(3015.75,1240.16) ; v1(3015.75,1448.82) 3023.62,1456.69 U6.11 3218.5,1456.69 R32.1 ; v1(3303.15,1129.92) 3303.15,1174.21 C48.2 ; R25.2 3334.65,1618.11 v1(3342.52,1610.24) ; C47.2 v1(3342.52,1744.09)
  Bottom Layer w12: v1(2492.13,708.66) v1(2492.13,1275.59)
  Bottom Layer w20: v1(2606.3,1367.13) 2625.98,1347.44 v1(2625.98,751.97) ; TP13.1 3015.75,881.89 v1(3015.75,1240.16) v1(3015.75,1448.82) 3015.75,1720.47 3007.87,1728.35 v1(2913.39,1728.35) ; v1(3303.15,751.97) v1(3303.15,1129.92) 3303.15,1570.87 v1(3342.52,1610.24) v1(3342.52,1744.09)
  other v1: 2519.68,688.98 2578.74,688.98 2637.8,688.98 2637.8,807.09 2460.63,1240.16 2519.68,1240.16 2322.83,1771.65
BLK: H6.7 U2.8 | length 1036.2
  Top Layer w8: v1(1716,748.6) 1949,748.6 2082.68,882.28 U2.8
  Bottom Layer w8: H6.7 1703.15,735.75 v1(1716,748.6)
DC: H6.6 U2.9 | length 961.9
  Top Layer w8: v1(1802,719.6) 1955,719.6 2114.17,878.77 U2.9
  Bottom Layer w8: v1(1802,719.6) 1802,372.8 H6.6
GHO: R1.1 TP5.1 U1.3 | length 155.4
  Top Layer w15: U1.3 1723.03,2049.8 TP5.1 1744.09,2070.87 R1.1
GHS: C27.1 R3.1 TP6.1 U1.4 | length 247.7
  Top Layer w15: C27.1 1661.22,1992.13 U1.4 1673.03,2031.69 TP6.1 R3.1
GLO: R4.1 TP8.1 U1.8 | length 555.8
  Top Layer w15: U1.8 1909.45,1767.72 1950,1808.27 1950,2018.6 1909.54,2059.06 TP8.1 1838.58,2062.99 R4.1
GND: C1.1 C2.1 C3.1 C4.1 C5.1 C6.1 C7.1 C8.1 C12.1 C13.1 C14.1 C15.1 C16.1 C21.1 C22.1 C23.1 C24.1 C25.1 C26.1 C28.1 C29.2 C30.2 C31.2 C32.2 C33.2 C35.1 C36.1 C37.1 C39.1 C40.1 C41.1 C42.2 C43.2 D2.1 D7.1 D8.2 H2.2 H3.2 H5.3 H6.0@1074.8,3019.68 H6.1 H7.5 L5.1 Q3.1 Q3.2 Q3.3 Q4.1 Q4.2 Q4.3 R5.1 R6.1 R7.1 R13.3 R17.2 R20.2 SW1.1 SW2.1 SW3.1 TP3.1 TP14.1 TP15.1 U1.7 U2.6 U2.30 U2.39 U3.3 U3.29 U4.1 U5.5 U5.6 U5.7 U5.8 U5.9 | length 20357.8
  Top Layer w10: 984.25,1575.79 1113.19,1575.79 1157.48,1531.5 U3.3 1271.65,1531.5 v3(1291.34,1511.81) ; SW1.1 1271.65,98.43 v1(1330.71,157.48) ; v1(1291.5,1262.13) 1291.5,1265.91 R17.2 ; v1(1409.45,236.22) 1440.94,236.22 H7.5
  Top Layer w12: 625.98,456.69 620.47,451.18 H5.3 687.4,177.17 C28.1 ; C42.2 R20.2 769.8,1427.17 799.21,1456.58 799.21,1586.61 TP14.1 ; U5.5 875,1685.04 984.25,1575.79 C37.1 C36.1 ; D8.2 972.44,1420.28 C36.1 ; C35.1 1182.96,1284.45 1129.81,1337.6 C43.2 1024.61,1411.42 C36.1 ; C31.2 1516.73,1343.49 1547.25,1374.02 1594.49,1374.02 v1(1618.11,1350.39)
  Top Layer w15: U2.6 2016.98,1114.17 2016.98,960.12 C29.2@2046.98,930.12
  Top Layer w20: U5.6 v1(1574.21,1742.72) R6.1 ; v1(1618.11,1350.39) 1629.61,1338.9 U2.39@1795.28,1338.9 ; U1.7 1773.03,1705.31 R7.1 1785.43,1692.91 v1(1830.71,1692.91) 1874.9,1692.91 1944.11,1762.13 1971.77,1762.13 C32.2 2006.12,1796.47 C26.1 2102.32,2074.8 C13.1 ; v1(1952.76,1661.42) 1956.38,1657.8 U2.30@1956.38,1562.99 ; v1(2043.31,885.83) 2046.98,889.5 C29.2@2046.98,930.12 ; v1(2149.6,141.73) 2152.56,144.69 C30.2 ; SW2.1 2153.54,51.18 v1(2165.35,39.37) ; v1(2354.33,78.74) 2362.2,70.87 SW3.1 2566.93,170.28 C33.2 2897.64,173.23 2925.2,145.67 2925.2,86.61 R13.3
  Top Layer w50: v1(198.82,1789.37) v1@192.91,1783.46 ; U4.1 590.35,646.65 C39.1 ; C7.1 C21.1 C22.1 ; U5.9@767.72,1789.37 767.72,1883.86 D2.1 ; U5.5 U5.6 U5.7 U5.8 875,1922.24 D2.1 ; TP3.1 625.98,456.69 570.87,456.69 ; C8.1 C6.1 C5.1 C4.1 C24.1 C25.1 C23.1 C22.1 ; Q3.3 Q3.2 ; Q4.3 1766.89,2520.51 1708.5,2578.91 1708.5,2671.69 Q3.2 ; H6.1 2303.15,440.94 2255.91,488.19 2255.91,602.36 ; L5.1 2369.68,633.46 2338.58,602.36 2255.91,602.36 ; C13.1 C12.1 C14.1 C15.1 ; TP15.1 2708.66,1956.69 R5.1 2788.39,2067.91 C15.1 ; C16.1 C15.1 ; v1@192.91,1783.46 D7.1 285.43,1875.98 C41.1 307.09,1905.51 H2.2 307.09,2461.61 C1.1 138.78,2667.38 437.01,2965.61 H3.2 523.98,3110.6 735.86,3110.6 C2.1 C3.1 1070.87,3023.62 1074.8,3019.68 1710.91,3019.68 1766.5,2964.1 1766.5,2893.7 Q3.1 Q3.2 ; v1@192.91,1783.46 169.29,1783.46 94.49,1708.66 94.49,720.47 168.31,646.65 C39.1 ; C39.1 354.33,539.37 437.01,456.69 570.87,456.69 ; 570.87,456.69 712.6,598.43 1050.2,598.43 C40.1 1142.72,602.36 2255.91,602.36 ; D2.1 858.27,1974.41 C22.1
  Bottom Layer w10: v3(1291.34,1468.5) 1287.4,1464.57 1287.4,1258.04 v1(1291.5,1262.13) 1366.14,1187.49 1366.14,279.53 v1(1409.45,236.22) v1(1330.71,157.48)
  Bottom Layer w20: v1(1952.76,1661.42) 1921.26,1692.91 v1(1830.71,1692.91) 1624.02,1692.91 v1(1574.21,1742.72) 1574.21,1394.29 v1(1618.11,1350.39) 1618.11,968.5 1657.48,929.13 2000,929.13 v1(2043.31,885.83) ; v1(2149.6,141.73) 2149.6,55.12 v1(2165.35,39.37) 2314.96,39.37 v1(2354.33,78.74) 2354.33,320.47 H6.1
  Bottom Layer w50: v1(198.82,1789.37) v3(746.06,1789.37) ; TP14.1 771.65,1765.47
  other v1: 1496.06,78.74 1771.65,78.74 1102.36,236.22 1751.97,688.98 1653.54,708.66 1338.58,748.03 1555.12,748.03 1318.9,984.25 1377.95,984.25 1594.49,984.25 1673.23,984.25 1751.97,984.25 1594.49,1062.99 1673.23,1062.99 1751.97,1062.99 1318.9,1082.68 1377.95,1082.68 1594.49,1141.73 1673.23,1141.73 1751.97,1141.73 236.22,2125.98 393.7,2125.98 236.22,2185.04 393.7,2185.04 236.22,2263.78 393.7,2263.78 236.22,2322.83 393.7,2322.83 1692.91,2854.33 1732.28,2854.33 1771.65,2854.33 1811.02,2854.33 1692.91,2893.7 1732.28,2893.7 1771.65,2893.7 1811.02,2893.7 1692.91,2933.07 1732.28,2933.07 1771.65,2933.07 1811.02,2933.07
  other v3: 1248.03,1468.5 1334.65,1468.5 1248.03,1511.81 1334.65,1511.81 1248.03,1555.12 1291.34,1555.12 1334.65,1555.12 746.06,1746.06 789.37,1746.06 789.37,1789.37
L_CS: H6.9 U2.4 | length 1171.7
  Top Layer w8: v1(1489,811.6) 1881,811.6 1956.69,887.29 U2.4
  Bottom Layer w8: v1(1489,811.6) 1489,385.8 H6.9
LED1: D4.2 U2.15 | length 1320.2
  Top Layer w8: U2.15 2307.09,1275.59 v1(2314.96,1267.72) ; v1(2346.46,515.75) 2350.6,511.61 2645.87,511.61 2748.03,409.45 D4.2
  Bottom Layer w8: v1(2314.96,1267.72) 2314.96,547.24 v1(2346.46,515.75)
LED2: D5.2 U2.20 | length 1425.5
  Top Layer w8: U2.20 v1(2405.51,1433.07) ; v1(2405.51,555.12) 2425.2,535.43 D5.2
  Bottom Layer w8: v1(2405.51,555.12) v1(2405.51,1433.07)
MCLR: C28.2 H5.1 R8.2 SW1.2 U2.18 | length 3381.3
  Top Layer w8: H5.1 467.72,62.99 964.57,62.99 SW1.2 1015.75,122.05 C28.2 ; R8.2@1222.44,183.18 R8.2 C28.2 ; v1(2188.98,1370.08) U2.18 ; v1(2244.09,314.96) 1354.22,314.96 1349.7,310.44 1061.84,310.44 1015.75,264.35 C28.2
  Bottom Layer w8: v1(2188.98,1370.08) 2188.98,448.82 2244.09,393.7 v1(2244.09,314.96)
MISO: H6.8 U2.5 | length 1057.2
  Top Layer w8: v1(1612,784.6) 1877,784.6 1988.19,895.79 U2.5
  Bottom Layer w8: H6.8 1603.15,775.75 v1(1612,784.6)
MOSI: H6.4 U2.11 | length 819.7
  Top Layer w8: v1(1997,694.6) 2177.17,874.76 U2.11
  Bottom Layer w8: v1(1997,694.6) 1997,377.8 H6.4
NetC1_2: C1.2 C2.2 C3.2 C41.2 D2.2 H2.1 H3.1 L1.1 R36.2 TP1.1 U5.1 | length 1876.8
  Top Layer w12: v1(929.13,1870.07) v1(1515.74,1870.07) ; v1(2066.93,1787.4) 2108.27,1787.4 R36.2
  Bottom Layer w12: H2.1 551.18,2000 681.11,1870.07 v1(929.13,1870.07) ; v1(1515.74,1870.07) 1984.26,1870.07 v1(2066.93,1787.4)
NetC9_1: C9.1 C10.1 C17.1 C18.1 C19.1 C20.1 D1.2 D3.1 H1.2 H4.2 R5.2 R24.1 R30.2 TP4.1 | length 1056.9
  Top Layer w8: v1(2582.68,1551.18) R24.1 ; v1(2594.49,1787.4) 2604.27,1797.18 2944.94,1797.18 R30.2 3039.36,1749.99 v1(3039.36,1763.77) ; TP4.1 3082.68,1915.35 D3.1
  Bottom Layer w8: v1(2582.68,1551.18) 2583.22,1551.72 2583.22,1776.13 v1(2594.49,1787.4) ; v1(3039.36,1763.77) 3039.37,1830.71 3066.93,1858.27 TP4.1
  other v5: 3720.47,2086.61 3799.21,2086.61 3877.95,2086.61 3720.47,2165.35 3799.21,2165.35 3877.95,2165.35 3720.47,2244.09 3799.21,2244.09 3877.95,2244.09
NetC9_2: C9.2 C10.2 C12.2 C13.2 C14.2 C15.2 C16.2 C17.2 C18.2 C19.2 C20.2 D3.2 H1.1 H4.1 L2.2 R2.1 R28.2 TP2.1 | length 720.4
  Top Layer w8: R28.2 v1(3366.14,1555.12)
  Bottom Layer w8: v1(3366.14,1555.12) 3389.76,1578.74 H1.1
NetC27_2: C27.2 U1.2 | length 261
  Top Layer w15: C27.2 1732.28,1881.89 1773.03,1922.64 U1.2
NetC29_1: C29.1 U2.7 | length 130.9
  Top Layer w15: C29.1 U2.7
NetC30_1: C30.1 R9.2 R10.1 SW2.2 | length 1783.6
  Top Layer w8: v1(1517.72,1206.69) R10.1 ; v1(1571,131.6) 1565,131.6 1562.87,133.73 1783.59,133.73 SW2.2 1895.67,120.08 R9.2 C30.1
  Bottom Layer w8: v1(1517.72,1206.69) 1517.72,450.79 1559.06,409.45 ; 1559.05,409.45 1567.53,400.97 1567.53,135.07 v1(1571,131.6)
NetC33_1: C33.1 R11.2 R12.1 SW3.2 | length 1489.7
  Top Layer w8: v1(1862.2,893.7) R12.1 ; v1(1863,253.6) 1878.6,238 2246.37,238 2305.12,179.25 R11.2 ; SW3.2 2305.12,116.14 R11.2 ; C33.1 R11.2
  Bottom Layer w8: v1(1862.2,893.7) 1862,893.5 1863,892.5 v1(1863,253.6)
NetC35_2: C35.2 H7.1 U3.7 U3.8 | length 1637.5
  Top Layer w8: C35.2 1185.04,1374.02 v1@1192,1380.98 ; v1(1193.62,1380.98) v1@1192,1380.98 ; U3.7 U3.8 v1@1192,1380.98 ; v1(1280,283.6) 1354,283.6 1362,291.6 1552,291.6 1562.99,280.61 H7.1
  Bottom Layer w8: v1(1193.62,1380.98) 1263,1311.6 1263,300.6 v1(1280,283.6)
NetC38_2: C38.2 R19.2 R20.1 U5.3 | length 440.7
  Top Layer w10: C38.2 610.24,1506.89 610.24,1724.41 628.54,1742.72 U5.3
  Top Layer w20: C38.2 638.78,1478.35 R20.1
NetC45_1: C45.1 R22.2 R24.2 U6.3 | length 713.3
  Top Layer w8: R22.2 2659.45,1236.97 2694.6,1201.81 v1(2811.21,1201.81) ; R24.2 2766.73,1551.18 C45.1 ; v1(2771.65,1522.25) C45.1 ; U6.3 2821.06,1506.69 C45.1
  Bottom Layer w8: v1(2771.65,1522.25) 2811.21,1482.69 v1(2811.21,1201.81)
NetC45_2: C45.2 R23.1 R27.2 U6.2 | length 373.8
  Top Layer w8: R23.1 2766.73,1614.17 C45.2 2824.21,1556.69 U6.2 2934.65,1556.69 2952.76,1574.8 R27.2
NetC46_1: C46.1 R26.2 TP16.1 U2.21 | length 754.2
  Top Layer w8: U2.21 2244.09,1460.44 2486.84,1460.44 TP16.1 ; v1(2491,1731.6) 2649.91,1731.6 C46.1 2658.46,1678.15 R26.2
  Bottom Layer w8: TP16.1 v1(2491,1731.6)
NetC47_1: C47.1 R29.1 TP17.1 U2.22 | length 1405
  Top Layer w8: U2.22 TP17.1 ; v1(2457,1787.71) 2484.47,1815.18 3066.71,1815.18 3137.8,1744.09 C47.1 3305.12,1691.93 R29.1
  Bottom Layer w8: TP17.1 2421.26,1751.97 v1(2457,1787.71)
NetC48_1: C48.1 R34.2 TP18.1 U2.23 | length 1523.6
  Top Layer w8: U2.23 TP18.1 ; v1(2346.46,1177.17) 2347.59,1176.03 3251.82,1176.03 C48.1 3252.95,1239.17 R34.2
  Bottom Layer w8: TP18.1 2346.46,1559.06 v1(2346.46,1177.17)
NetC49_1: C49.1 R36.1 R39.1 TP19.1 U2.25 | length 562.1
  Top Layer w8: U2.25 v1(2114.17,1661.42) ; C49.1 2115.16,1853.35 2139.54,1828.96 2139.66,1828.96 2167.32,1801.3 R36.1 ; R39.1 2116.14,1738.07 2167.32,1789.26 R36.1 ; TP19.1 2224.41,1795.28 R36.1
  Bottom Layer w8: v1(2114.17,1661.42) 2114.17,1744.09 2157.48,1787.4 TP19.1
NetC50_1: C50.1 R40.1 R41.2 U6.5 | length 279.7
  Top Layer w8: R40.1 R41.2 2711.61,1367.13 C50.1 2730.12,1406.69 U6.5
NetD1_1: D1.1 R2.2 | length 57.1
  Top Layer w8: R2.2 D1.1
NetD4_1: D4.1 R14.1 | length 85
  Top Layer w8: R14.1 2785.43,462.6 D4.1
NetD5_1: D5.1 R15.1 | length 85
  Top Layer w8: R15.1 2785.43,588.58 D5.1
NetD6_1: D6.1 R16.1 | length 59.9
  Top Layer w8: D6.1 1375.98,1281.5 R16.1
NetD6_2: D6.2 U3.12 | length 108.8
  Top Layer w8: U3.12 1311.02,1401.57 D6.2
NetD7_2: D7.2 L3.1 U5.2
NetD8_1: D8.1 R21.2 | length 85
  Top Layer w8: D8.1 1025.59,1336.61 R21.2
NetH7_2: H7.2 U3.5 | length 1794.4
  Top Layer w8: v1(1133.86,1472.44) 1164.64,1472.44 1182.55,1490.35 1199.01,1490.35 U3.5 ; v1(1217.44,235.04) 1237.88,214.6 1325.81,214.6 1422.4,118.01 1503.41,118.01 1537.4,152 H7.2
  Bottom Layer w8: v1(1133.86,1472.44) 1133.86,1366.14 1133.56,1365.85 1217.44,1281.97 v1(1217.44,235.04)
NetH7_3: H7.3 U3.4 | length 1708.8
  Top Layer w8: v1(1158,1502.6) 1162,1502.6 1163,1501.6 1173.21,1511.81 U3.4 ; v1(1244,261.6) 1265.41,240.19 1336.41,240.19 1433,143.6 1503.41,143.6 1511.81,152 H7.3
  Bottom Layer w8: v1(1158,1502.6) 1159.64,1500.96 1159.64,1375.96 1244,1291.6 v1(1244,261.6)
NetH8_1: H8.1 R35.1 R38.2 | length 502.5
  Top Layer w8: R35.1 3364.17,1366.14 R38.2 3757.87,1372.05 H8.1
NetH8_2: H8.2 R33.1 R38.1 | length 535.1
  Top Layer w8: R33.1 3364.17,1429.13 R38.1 3679.13,1423.23 H8.2
NetL2_1: L2.1 Q1.1 Q1.2 Q1.3 Q2.1 Q2.2 Q2.3 Q3.5 Q4.5 R3.2 TP7.1 | length 81.4
  Top Layer w15: R3.2 1649.61,2318.9 v2(1653.54,2322.83)
  other v2: 1574.8,2322.83 1614.17,2322.83 1850.39,2342.52 1889.76,2342.52 1929.13,2342.52 1968.5,2342.52 2007.87,2342.52 1574.8,2362.2 1614.17,2362.2 1653.54,2362.2 1850.39,2381.89 1889.76,2381.89 1929.13,2381.89 1968.5,2381.89 2007.87,2381.89 1574.8,2401.57 1614.17,2401.57 1653.54,2401.57 1850.39,2421.26 1889.76,2421.26 1928.74,2420.47 1968.5,2421.26 2007.87,2421.26 1574.8,2440.94 1614.17,2440.94 1653.54,2440.94 1850.39,2460.63 1889.76,2460.63 1929.13,2460.63 1968.5,2460.63 2007.87,2460.63 1574.8,2480.31 1614.17,2480.31 1653.54,2480.31 1850.39,2500 1889.76,2500 1929.13,2500 1968.5,2500 2007.87,2500 1574.8,2519.68 1614.17,2519.68 1653.54,2519.68 1574.8,2559.06 1614.17,2559.06 1653.54,2559.06 1574.8,2598.43 1614.17,2598.43 1653.54,2598.43 1850.39,2618.11 1889.76,2618.11 1929.13,2618.11 1968.5,2618.11 2007.87,2618.11 1574.8,2637.8 1614.17,2637.8 1653.54,2637.8 1850.39,2657.48 1889.76,2657.48 1929.13,2657.48 1968.5,2657.48 2007.87,2657.48 1574.8,2677.17 1614.17,2677.17 1653.54,2677.17 1850.39,2696.85 1889.76,2696.85 1929.13,2696.85 1968.5,2696.85 2007.87,2696.85 1574.8,2716.54 1614.17,2716.54 1653.54,2716.54 1850.39,2736.22 1889.76,2736.22 1929.13,2736.22 1968.5,2736.22 2007.87,2736.22 1574.8,2755.91 1614.17,2755.91 1653.54,2755.91 1850.39,2775.59 1889.76,2775.59 1929.13,2775.59 1968.5,2775.59 2007.87,2775.59 1574.8,2795.28 1614.17,2795.28 1653.54,2795.28
NetQ1_4: Q1.4 Q2.4 R1.2 TP21.1 | length 973.7
  Top Layer w15: Q1.4 1520.52,2515.11 v1(1533,2527.6) ; Q2.4 1520.52,2797.11 v1(1533,2809.6) ; v1(1533,2225.6) 1573.61,2225.6 1596.24,2202.97 1703.96,2202.97 R1.2
  Bottom Layer w15: TP21.1 1533,2888.26 v1(1533,2809.6) v1(1533,2527.6) v1(1533,2225.6)
NetQ3_4: Q3.4 Q4.4 R4.2 TP22.1 | length 568.8
  Top Layer w15: Q3.4 1812.42,2583.76 1812.42,2362.2 1796.48,2346.26 Q4.4 1766.89,2314.8 R4.2 1926.18,2243.11 TP22.1
NetR6_2: R6.2 TP9.1 U1.5 U2.12 | length 1092.7
  Top Layer w8: TP9.1 1671.26,1639.76 R6.2 1671.26,1765.94 U1.5 ; v1(1859.41,1178.31) 1862.2,1181.1 U2.12
  Bottom Layer w8: TP9.1 1763.78,1527.56 1763.78,1221.61 1807.09,1178.31 v1(1859.41,1178.31)
NetR7_2: R7.2 TP10.1 U1.6 U2.13 | length 1024.6
  Top Layer w8: U1.6 1723.03,1704.13 R7.2 1730.32,1631.89 TP10.1 ; v1(1862.2,1216.53) 1866.13,1212.6 U2.13
  Bottom Layer w8: TP10.1 1795.28,1566.93 1795.28,1228.34 1807.09,1216.53 v1(1862.2,1216.53)
NetR13_2: R13.2 U2.24 | length 1937.6
  Top Layer w8: v1(2145.67,1500) U2.24 ; v1(2169.29,263.78) 2775.59,263.78 R13.2
  Bottom Layer w8: v1(2145.67,1500) 2145.67,287.4 v1(2169.29,263.78)
NetR17_1: R17.1 U3.11 | length 92.8
  Top Layer w8: U3.11 1291.34,1356.3 R17.1
NetR18_1: R18.1 U3.9 | length 86.3
  Top Layer w8: R18.1 1250.19,1338.77 1250.19,1419.48 U3.9
NetR23_2: R23.2 R26.1 U6.1 | length 265.8
  Top Layer w8: R23.2 2659.45,1617.36 2687.94,1645.86 2691.13,1645.86 2710.63,1665.35 R26.1 2738.19,1649.61 2818.31,1649.61 U6.1
NetR25_1: R25.1 R28.1 U6.12 | length 253.3
  Top Layer w8: U6.12 3205.51,1506.69 R28.1 R25.1
NetR29_2: R29.2 R31.1 U6.14 | length 248.2
  Top Layer w8: U6.14 3083.66,1670.28 R31.1 3248.03,1675.2 R29.2
NetR30_1: R30.1 R31.2 U6.13 | length 268.8
  Top Layer w8: R31.2 3075.55,1726.38 3047.06,1697.88 3047.06,1694.69 3027.56,1675.2 R30.1 3015.75,1562.99 3022.05,1556.69 U6.13
NetR32_2: R32.2 R33.2 U6.10 | length 265.6
  Top Layer w8: U6.10 3231.5,1406.69 R33.2 3253.94,1440.94 3273.43,1460.44 3276.62,1460.44 3305.12,1488.93 R32.2
NetR34_1: R34.1 R37.2 U6.8 | length 257.8
  Top Layer w8: U6.8 3250.39,1306.69 R37.2 3253.94,1291.34 3273.43,1271.84 3276.62,1271.84 3305.12,1243.35 R34.1
NetR35_2: R35.2 R37.1 U6.9 | length 263.4
  Top Layer w8: U6.9 3244.49,1356.69 R35.2 3253.94,1357.52 3277,1334.46 3285.62,1334.46 3305.12,1314.96 R37.1
PGC2: H5.5 U2.35 | length 2313.2
  Top Layer w8: v1(820.47,509.13) 836.94,525.6 v1(1444,525.6) ; v1(1462,1467.6) 1792.24,1467.6 U2.35
  Bottom Layer w8: H5.5 v1(820.47,509.13) ; v1(1444,525.6) 1462,543.6 v1(1462,1467.6)
PGD2: H5.4 U2.34 | length 2434.8
  Top Layer w8: v1(739,545.6) 1404,545.6 v1(1411,552.6) ; v1(1432.07,1496.6) 1794.74,1496.6 U2.34
  Bottom Layer w8: H5.4 720.47,527.07 v1(739,545.6) ; v1(1411,552.6) 1432.07,573.67 v1(1432.07,1496.6) v1@1431.54,1496.06
PV: C4.2 C5.2 C6.2 C7.2 C8.2 C21.2 C22.2 C23.2 C24.2 C25.2 L1.2 Q1.5 Q2.5
REF_1V65: C51.1 R22.1 TP20.1 U2.26 U6.6 U6.7 | length 1457.1
  Top Layer w8: U2.26 2082.68,1673.23 2102.36,1692.91 2102.68,1692.6 v1(2611,1692.6) ; R22.1 TP20.1 C51.1 2861.22,1256.89 U6.7 U6.6
  Bottom Layer w8: v1(2611,1692.6) 2665.04,1692.6 2665.35,1692.91 2724.41,1633.86 2724.41,1532.19 2775.59,1481.01 TP20.1
RST: H6.5 U2.10 | length 869.3
  Top Layer w8: v1(1908,691.6) 1953,691.6 2145.67,884.27 U2.10
  Bottom Layer w8: H6.5 1903.15,686.75 v1(1908,691.6)
RXD: U2.38 U3.25 | length 791.2
  Top Layer w8: U3.25 1291.34,1629.94 1303,1641.6 1343.57,1641.6 1350,1635.16 v1(1350,1640.6) ; v1(1376,1395.6) 1705.53,1395.6 1731.05,1370.08 U2.38
  Bottom Layer w8: v1(1350,1640.6) 1361,1640.6 1372,1629.6 1372,1399.6 v1(1376,1395.6)
SCLK: H6.3 U2.14 | length 1007.3
  Top Layer w8: v1(2113.5,1244.09) U2.14
  Bottom Layer w8: H6.3 2103.15,1233.74 v1(2113.5,1244.09)
SW1: R10.2 U2.41 | length 237.8
  Top Layer w8: R10.2 1596.46,1275.59 U2.41
SW2: R12.2 U2.1 | length 131.9
  Top Layer w8: R12.2 U2.1
T_CS: H6.10 U2.3 | length 1255.6
  Top Layer w8: v1(1397,836.6) 1397.78,837.38 1499.68,837.38 1500.46,836.6 1877,836.6 1925.2,884.8 U2.3
  Bottom Layer w8: v1(1397,836.6) 1385,824.6 1385,389.8 H6.10
T_IRQ: H6.11 U2.2 | length 1300.1
  Top Layer w8: v1(1339,863.6) 1873,863.6 1893.89,884.49 1893.89,1113.98 U2.2
  Bottom Layer w8: H6.11 1303.15,827.75 v1(1339,863.6)
TXD: U2.37 U3.26 | length 813.8
  Top Layer w8: U3.26 1271.65,1647.25 1290.78,1666.38 1376.22,1666.38 v1(1388,1654.6) ; v1(1401.78,1423.07) 1722.6,1423.07 1744.09,1401.57 U2.37
  Bottom Layer w8: v1(1388,1654.6) 1388,1436.71 1401.64,1423.07 v1(1401.78,1423.07)
VDD: C36.2 C37.2 R16.2 R18.2 U3.6 | length 761.7
  Top Layer w8: v1(1077.76,1436.35) C36.2 ; C37.2 C36.2 ; v1(1190,1233.6) 1196.2,1233.6 R18.2 1248.03,1236.22 1259.84,1224.41 R16.2 ; U3.6 1199.01,1470.66 1185.5,1470.66 1161.43,1446.6 1103.6,1446.6 C36.2
  Bottom Layer w8: v1(1077.76,1436.35) 1077.76,1245.84 1090,1233.6 v1(1190,1233.6)
pads on no net: H1.3 H2.3 H6.0@1074.8,411.02 H6.0@2531.5,411.02 H6.0@2531.5,3019.68 H7. H7.4 P1.1 P2.1 P3.1 P4.1 U2.19 U2.27 U2.28 U2.31 U2.32 U2.33 U2.36 U2.42 U2.43 U2.44 U3.1 U3.2 U3.10 U3.13 U3.14 U3.15 U3.16 U3.17 U3.18 U3.19 U3.20 U3.21 U3.22 U3.23 U3.24 U3.27 U3.28 U5.4

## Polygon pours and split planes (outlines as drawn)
NetC1_2 on Top Layer "NETC1_2_L01_P038" (solid, pour order 38): 472.44,1948.82 393.7,1948.82 374.02,1929.13 374.02,1870.08 393.7,1850.39 610.24,1850.39 629.92,1830.71 688.98,1830.71 708.66,1850.39 708.66,1889.76 748.03,1929.13 748.03,1988.19 728.35,2007.87 632.58,2007.87 629.92,2010.54
NetC9_2 on Top Layer "NETC9_2_L01_P036" (solid, pour order 36): 3208.66,1988.19 3228.35,2007.87 3346.46,2007.87 3346.46,2106.3 3484.25,2106.3 3484.25,2047.24 3425.2,1988.19 3405.51,1988.19 3405.51,1929.13 3208.66,1929.13
NetC9_1 on Top Layer "NETC9_1_L01_P034" (solid, pour order 34): 2952.76,2106.3 2952.76,1850.39 3011.81,1791.34 3838.58,1791.34 3917.32,1870.08 3917.32,2303.15 3523.62,2303.15 3523.62,1929.13 3503.94,1909.45 3208.66,1909.45 3188.98,1929.13 3188.98,2007.87 3208.66,2027.56 3307.09,2027.56 3326.77,2047.24 3326.77,2106.3
NetC9_1 on Top Layer "NETC9_1_L01_P024" (solid, pour order 24): 2775.59,3031.5 2795.28,3051.18 3444.88,3051.18 3681.1,2814.96 3818.9,2814.96 3858.27,2775.59 3858.27,2716.54 3818.9,2677.17 3523.62,2677.17 3326.77,2874.02 2795.28,2874.02 2775.59,2893.7
3V3 on Top Layer "3V3_L01_P022" (solid, pour order 22): 787.4,748.03 787.4,629.92 984.25,629.92 984.25,826.77 1181.1,826.77 1181.1,1220.47 1141.73,1259.84 1141.73,1299.21 1003.94,1299.21 1003.94,984.25 905.51,885.83 905.51,748.03
9V5 on Top Layer "9V5_L01_P020" (solid, pour order 20): 236.22,1318.9 492.13,1318.9 511.81,1299.21 866.14,1299.21 866.14,807.09 236.22,807.09
NetC1_2 on Top Layer "NETC1_2_L01_P000" (solid, pour order 0): 511.81,2125.98 472.44,2165.35 472.44,2480.31 354.33,2598.43 354.33,2755.91 551.18,2952.76 551.18,3031.5 590.55,3070.87 669.29,3070.87 787.4,2952.76 984.25,2952.76 1102.36,2834.65 1102.36,2637.8 787.4,2637.8 708.66,2559.06 629.92,2480.31 629.92,2165.35 590.55,2125.98
PV on Top Layer "PV_L01_P002" (solid, pour order 2): 629.92,2145.67 629.92,2244.09 866.14,2480.31 1141.73,2480.31 1220.47,2559.05 1220.47,2795.28 1259.84,2834.65 1456.69,2834.65 1456.69,2283.46 1535.43,2204.72 1574.8,2204.72 1574.8,2145.67
NetL2_1 on Top Layer "NETL2_1_L01_P004" (solid, pour order 4): 1476.38,2322.83 1496.06,2303.15 1653.54,2303.15 1673.23,2322.83 1673.23,2795.28 1653.54,2814.96 1555.12,2814.96 1476.38,2736.22
NetL2_1 on Top Layer "NETL2_1_L01_P008" (solid, pour order 8): 1850.39,2814.96 1830.71,2795.28 1830.71,2322.83 1850.39,2303.15 2106.3,2303.15 2244.09,2440.94 2244.09,2677.17 2106.3,2814.96
NetC9_2 on Top Layer "NETC9_2_L01_P010" (solid, pour order 10): 2460.63,2696.85 2440.94,2677.17 2440.94,2165.35 2460.63,2145.67 3307.09,2145.67 3350.39,2102.36 3484.25,2102.36 3484.25,2145.67 3484.25,2677.17 3444.88,2716.54 2480.32,2716.54
NetC9_2 on Top Layer "NETC9_2_L01_P012" (solid, pour order 12): 3484.25,2677.17 3838.58,2677.16 3877.95,2637.8 3877.95,2500 3838.58,2460.63 3484.25,2460.63 3464.57,2480.31 3464.57,2657.48
NetC1_2 on Top Layer "NETC1_2_L01_P014" (solid, pour order 14): 472.44,1988.19 472.44,1850.39 629.92,1850.39 629.92,2027.56 629.92,2224.41 472.44,2224.41
NetD7_2 on Top Layer "NETD7_2_L01_P016" (solid, pour order 16): 679.13,1761.81 698.82,1781.5 698.82,1801.18 679.13,1820.87 383.86,1820.87 364.17,1801.18 364.17,1732.28 344.49,1712.6 246.06,1712.6 216.54,1683.07 216.54,1564.96 236.22,1545.28 472.44,1545.28 492.13,1564.96 492.13,1712.6 541.34,1761.81
AGND on Top Layer "AGND_L01_P048" (solid, remove dead copper, pour order 48): 2480.32,669.29 2440.94,708.66 2440.94,1653.54 2401.57,1692.91 2125.98,1692.91 2125.98,1850.39 2165.35,1889.76 2283.46,1889.76 2401.57,1771.65 3346.46,1771.65 3385.83,1732.28 3385.83,708.66 3346.46,669.29
GND on Top Layer "GND_L01_P050" (solid, remove dead copper, pour order 50): 0,3149.61 0,0 3897.64,0 3937.01,39.37 3937.01,3149.61
NetC9_1 on Bottom Layer "NETC9_1_L02_P032" (solid, pour order 32): 3759.84,2814.96 3720.47,2775.59 3720.47,2696.85 3582.68,2559.06 3582.68,2027.56 3622.05,1988.19 3937.01,1988.19 3937.01,2814.96
NetL2_1 on Bottom Layer "NETL2_1_L02_P006" (solid, pour order 6): 2047.24,2795.28 2027.56,2814.96 1574.8,2814.96 1555.12,2795.28 1555.12,2322.83 1574.8,2303.15 2027.56,2303.15 2047.24,2322.83
AGND on Bottom Layer "AGND_L02_P046" (solid, remove dead copper, pour order 46): 2480.32,669.29 2440.94,708.66 2440.94,1653.54 2401.57,1692.91 2125.98,1692.91 2125.98,1850.39 2165.35,1889.76 2283.46,1889.76 2401.57,1771.65 3346.46,1771.65 3385.83,1732.28 3385.83,708.66 3346.46,669.29
GND on Bottom Layer "GND_L02_P052" (solid, remove dead copper, pour order 52): 0,3149.61 0,0 3937.01,0 3937.01,3149.61

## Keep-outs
Keep-Out Layer:
  the board outline again, w10

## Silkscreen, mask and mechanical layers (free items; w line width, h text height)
Top Overlay:
  text "-" at 299.21,3007.87 h30
  text "+" at 748.03,3003.94 h30
  text "-" at 3862.2,2866.14 h30
  text "+" at 3866.14,2401.57 h30
  text "PGC" at 834.65,267.72 h30 r90
  text "3V3" at 535.43,263.78 h30 r90
  text "GND" at 629.92,263.78 h30 r90
  text "PGD" at 732.28,263.78 h30 r90
  text "MCLR" at 429.13,259.84 h30 r90
Top Solder:
  text "Synchronize Buck Converter" at 3157.48,401.57 h30
  text "Designed By Guo Wei" at 3251.97,354.33 h30
Mechanical 1:
  the board outline again, w10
